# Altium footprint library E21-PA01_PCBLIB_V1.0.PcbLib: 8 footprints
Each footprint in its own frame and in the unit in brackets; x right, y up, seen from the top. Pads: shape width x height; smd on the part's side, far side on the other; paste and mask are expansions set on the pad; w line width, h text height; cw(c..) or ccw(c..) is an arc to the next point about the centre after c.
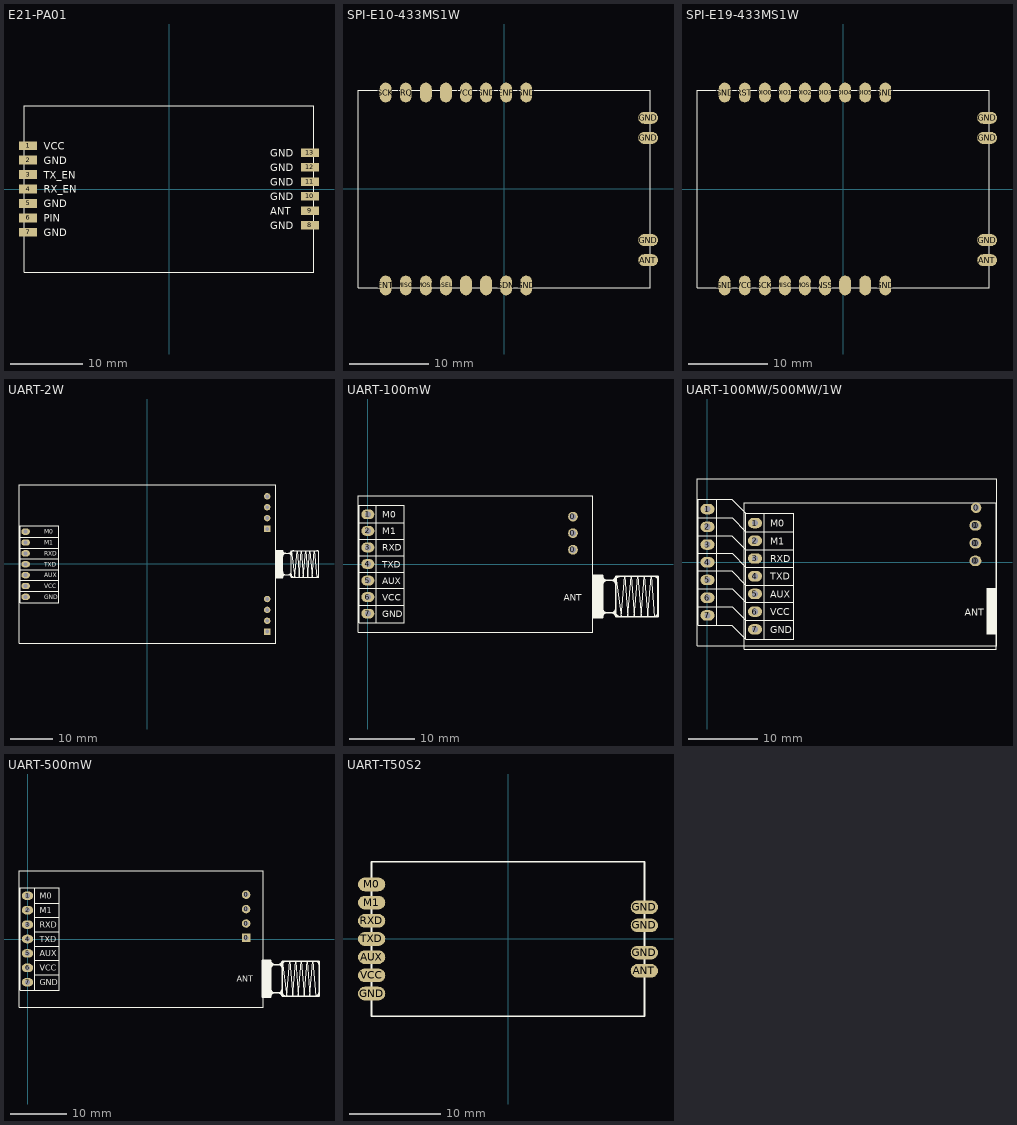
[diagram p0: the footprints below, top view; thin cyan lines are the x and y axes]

## E21-PA01 [mm]
pads (13):
  rect 2.5x1.2 smd: 1(-19.5,6) 2(-19.5,4) 3(-19.5,2) 4(-19.5,0) 5(-19.5,-2) 6(-19.5,-4) 7(-19.5,-6) 8(19.5,-5) 9(19.5,-3) 10(19.5,-1) 11(19.5,1) 12(19.5,3) 13(19.5,5)
TopOverlay:
  lines w0.1: -20,-11.5 20,-11.5 20,11.5 -20,11.5 -20,-11.5
  text "GND" at -17.35,3.45 h1
  text "TX_EN" at -17.35,1.45 h1
  text "PIN" at -17.35,-4.55 h1
  text "GND" at -17.35,-6.55 h1
  text "VCC" at -17.35,5.45 h1
  text "RX_EN" at -17.35,-0.55 h1
  text "GND" at -17.35,-2.55 h1
  text "GND" at 14,4.45 h1
  text "ANT" at 14,-3.55 h1
  text "GND" at 14,-1.55 h1
  text "GND" at 14,0.45 h1
  text "GND" at 14,2.45 h1
  text "GND" at 14,-5.55 h1

## SPI-E10-433MS1W [mm]
pads (20):
  oval 2.5x1.5 smd: ANT(18.2,-9) GND(18.2,-6.46) GND(18.2,6.46) GND(18.2,9)
  oval 1.5x2.5 smd: ENP(0.24,12.2) ENT(-15,-12.2) GND(-2.3,12.2) GND(2.78,-12.2) GND(2.78,12.2) GPIO0(-7.38,12.2) GPIO1(-9.92,12.2) GPIO2(-4.84,-12.2) GPIO3(-2.3,-12.2) IRQ(-12.46,12.2) MISO(-12.46,-12.2) MOSI(-9.92,-12.2) nSEL(-7.38,-12.2) SCK(-15,12.2) SDN(0.24,-12.2) VCC(-4.84,12.2)
TopOverlay:
  lines w0.1: -18.5,-12.5 18.5,-12.5 18.5,12.5 -18.5,12.5 -18.5,-12.5

## SPI-E19-433MS1W [mm]
pads (22):
  oval 2.5x1.5 smd: ANT(18.2,-9) GND(18.2,-6.46) GND(18.2,6.46) GND(18.2,9)
  oval 1.5x2.5 smd: CONT1(0.24,-12.2) CONT2(2.78,-12.2) DIO0(-9.92,12.2) DIO1(-7.38,12.2) DIO2(-4.84,12.2) DIO3(-2.3,12.2) DIO4(0.24,12.2) DIO5(2.78,12.2) GND(-15,-12.2) GND(-15,12.2) GND(5.32,-12.2) GND(5.32,12.2) MISO(-7.38,-12.2) MOSI(-4.84,-12.2) NSS(-2.3,-12.2) RST(-12.46,12.2) SCK(-9.92,-12.2) VCC(-12.46,-12.2)
TopOverlay:
  lines w0.1: -18.5,-12.5 -18.5,12.5 18.5,12.5 18.5,-12.5 -18.5,-12.5

## UART-2W [mm]
pads (18):
  oval 2x1.5 hole 0.9: 1(-28.46,7.56) 2(-28.46,5.02) 3(-28.46,2.48) 4(-28.46,-0.06) 5(-28.46,-2.6) 6(-28.46,-5.14) 7(-28.46,-7.68)
  rect 4.5x1.2 on Top Overlay: 1(27.41,0)
  rect 4.5x2 on Top Overlay: 2(27.41,-3.15) 2(27.41,3.15)
  rect 1.5x1.5 hole 0.9: 8(28,-15.81) 12(28,8.19)
  round 1.5 hole 0.9: 8(28,-13.27) 10(28,-10.73) 11(28,-8.19) 13(28,10.73) 14(28,13.27) 15(28,15.81)
TopOverlay:
  rectangle: 30.1,-3.25 31.6,3.25
  rectangle: 30.1,-3.245 31.6,3.255
  lines w0.1: -29.76,-6.4 -24.55,-6.4 ; -29.76,-3.82 -24.5,-3.82 ; -29.76,-1.32 -24.45,-1.32 ; -29.76,1.21 -24.4,1.21 ; -29.76,3.73 -24.5,3.73 ; -29.76,6.28 -24.75,6.28 ; -25,-6.4 -20.71,-6.4 ; -25,-3.82 -20.71,-3.82 ; -25,-1.32 -20.71,-1.32 ; -25,1.21 -20.71,1.21 ; -25,3.73 -20.71,3.73 ; -25,6.28 -20.71,6.28 ; 34.45,-3.1 34.97,3.1 ; 34.45,-3.1 33.6,3.1 34.45,-3.1 ; 34.45,-3.1 34.97,3.1 ; 34.97,3.1 35.48,-3.1 ; 34.97,3.1 35.48,-3.1 ; 35.48,-3.1 35.99,3.1 ; 35.48,-3.1 35.99,3.1 ; 35.99,3.1 36.47,-3.1 ; 35.99,3.1 36.47,-3.1 ; 36.47,-3.1 36.99,3.1 ; 36.47,-3.1 36.99,3.1 ; 36.99,3.1 37.5,-3.1 ; 36.99,3.1 37.5,-3.1 ; 37.5,-3.1 37.99,3.1 ; 37.5,-3.1 37.99,3.1 ; 37.99,3.1 38.51,-3.1 ; 37.99,3.1 38.51,-3.1 ; 38.51,-3.1 39.03,3.1 ; 38.51,-3.1 39.03,3.1 ; 39.03,3.1 39.54,-3.1 39.03,3.1 ; -30,-18.5 -30,18.5 30,18.5 30,-18.5 -30,-18.5 ; -29.76,-9.06 -29.76,8.94 -25,8.94 -20.71,8.94 -20.71,-9.06 -25,-9.06 -29.76,-9.06
  lines w0.254: 30.1,-3.25 31.6,-3.25 ; 30.1,-3.25 30.1,3.25 ; 30.1,-3.25 31.6,-3.25 ; 30.1,-3.25 30.1,3.25 ; 30.1,3.25 31.6,3.25 ; 30.1,3.25 31.6,3.25 ; 31.6,-3.25 31.6,3.25 ; 31.6,-3.25 31.6,3.25 ; 31.6,-1.85 ccw(c32.25,-1.85) 32.25,-2.5 ; 31.6,-1.85 ccw(c32.25,-1.85) 32.25,-2.5 ; 31.6,-1.85 31.6,-1.48 31.6,-1.85 ; 31.6,1.8 cw(c32.3,1.8) 32.3,2.5 ; 31.6,1.8 cw(c32.3,1.8) 32.3,2.5 ; 31.6,1.8 31.6,0.88 31.6,1.8 ; 31.6,3.13 ccw(c32.23,3.13) 32.23,2.5 ; 31.6,3.13 ccw(c32.23,3.13) 32.23,2.5 ; 31.6,3.13 31.6,3.25 ; 31.6,3.13 31.6,3.25 ; 32.15,-2.5 ccw(c32.15,-3.05) 31.6,-3.05 cw(c32.15,-3.05) 32.15,-2.5 ; 32.15,-2.5 33,-2.5 ; 32.15,-2.5 33,-2.5 ; 32.23,2.5 33,2.5 ; 32.23,2.5 33,2.5 ; 32.25,-2.5 32.97,-2.5 ; 32.25,-2.5 32.97,-2.5 ; 32.3,2.5 33,2.5 ; 32.3,2.5 33,2.5 ; 32.97,-2.5 ccw(c32.97,-1.87) 33.6,-1.87 cw(c32.97,-1.87) 32.97,-2.5 ; 33,-2.5 cw(c33,-3.1) 33.6,-3.1 ; 33,-2.5 cw(c33,-3.1) 33.6,-3.1 ; 33,2.5 cw(c33,1.9) 33.6,1.9 ccw(c33,1.9) 33,2.5 ; 33,2.5 ccw(c33,3.1) 33.6,3.1 ; 33,2.5 ccw(c33,3.1) 33.6,3.1 ; 33.6,-3.1 33.6,3.1 ; 33.6,-3.1 40.1,-3.1 ; 33.6,-3.1 33.6,3.1 ; 33.6,-3.1 40.1,-3.1 ; 33.6,3.1 40.1,3.1 ; 33.6,3.1 40.1,3.1 ; 34.28,-3.1 cw(c34.28,-2.42) 33.6,-2.42 ccw(c34.28,-2.42) 34.28,-3.1 ; 34.28,-3.1 34.43,-3.1 34.28,-3.1 ; 39.48,-3.1 ccw(c39.48,-2.48) 40.1,-2.48 cw(c39.48,-2.48) 39.48,-3.1 ; 39.48,-3.1 39.25,-3.1 39.48,-3.1 ; 39.56,3.1 cw(c39.56,2.56) 40.1,2.56 ccw(c39.56,2.56) 39.56,3.1 ; 39.56,3.1 39.16,3.1 39.56,3.1 ; 40.1,-3.1 40.1,3.1 ; 40.1,-3.1 40.1,3.1 ; 31.43,-2.5 33.6,-2.5 31.43,-2.5 ; 31.6,2.5 33.6,2.5 31.6,2.5 ; 33.6,2.49 cw(c34.21,2.49) 34.21,3.1 ccw(c34.21,2.49) 33.6,2.49
  text "M0" at -24.11,7.02 h1
  text "M1" at -24.11,4.48 h1
  text "RXD" at -24.11,1.94 h1
  text "TXD" at -24.11,-0.6 h1
  text "AUX" at -24.11,-3.14 h1
  text "VCC" at -24.11,-5.68 h1
  text "GND" at -24.11,-8.22 h1

## UART-100mW [mm]
pads (10):
  round 1.5 hole 1: 0(31.49,2.19) 0(31.49,4.73) 0(31.49,7.27)
  oval 2x1.5 hole 0.9: 1(0,7.62) 2(0,5.08) 3(0,2.54) 4(0,0) 5(0,-2.54) 6(0,-5.08) 7(0,-7.62)
TopOverlay:
  rectangle: 34.54,-8.25 36.04,-1.75
  rectangle: 34.54,-8.245 36.04,-1.745
  lines w0.1: 38.89,-8.1 39.41,-1.9 ; 38.89,-8.1 38.04,-1.9 38.89,-8.1 ; 38.89,-8.1 39.41,-1.9 ; 39.41,-1.9 39.92,-8.1 ; 39.41,-1.9 39.92,-8.1 ; 39.92,-8.1 40.43,-1.9 ; 39.92,-8.1 40.43,-1.9 ; 40.43,-1.9 40.91,-8.1 ; 40.43,-1.9 40.91,-8.1 ; 40.91,-8.1 41.43,-1.9 ; 40.91,-8.1 41.43,-1.9 ; 41.43,-1.9 41.94,-8.1 ; 41.43,-1.9 41.94,-8.1 ; 41.94,-8.1 42.43,-1.9 ; 41.94,-8.1 42.43,-1.9 ; 42.43,-1.9 42.95,-8.1 ; 42.43,-1.9 42.95,-8.1 ; 42.95,-8.1 43.47,-1.9 ; 42.95,-8.1 43.47,-1.9 ; 43.47,-1.9 43.98,-8.1 43.47,-1.9 ; -1.51,-10.5 34.558,-10.5 34.558,10.5 -1.51,10.5 -1.51,-10.5
  lines w0.127: -1.3,-9 1.3,-9 1.3,9 -1.3,9 -1.3,-9
  lines w0.152: -1.31,3.8 1.3,3.8 ; -1.3,-3.76 1.3,-3.76 5.59,-3.76 ; -1.29,-6.34 1.3,-6.34 5.59,-6.34 ; -1.29,-1.26 1.3,-1.26 5.59,-1.26 ; -1.29,1.27 1.3,1.27 5.59,1.27 ; -1.29,6.36 1.3,6.36 ; 1.3,-9 5.59,-9 5.59,9 1.3,9 ; 1.3,3.79 5.59,3.79 ; 1.3,6.34 5.59,6.34
  lines w0.254: 34.54,-8.25 36.04,-8.25 ; 34.54,-8.25 34.54,-1.75 ; 34.54,-8.25 36.04,-8.25 ; 34.54,-8.25 34.54,-1.75 ; 34.54,-1.75 36.04,-1.75 ; 34.54,-1.75 36.04,-1.75 ; 36.04,-8.25 36.04,-1.75 ; 36.04,-8.25 36.04,-1.75 ; 36.04,-6.85 ccw(c36.69,-6.85) 36.69,-7.5 ; 36.04,-6.85 ccw(c36.69,-6.85) 36.69,-7.5 ; 36.04,-6.85 36.04,-6.48 36.04,-6.85 ; 36.04,-3.2 cw(c36.74,-3.2) 36.74,-2.5 ; 36.04,-3.2 cw(c36.74,-3.2) 36.74,-2.5 ; 36.04,-3.2 36.04,-4.12 36.04,-3.2 ; 36.04,-1.87 ccw(c36.67,-1.87) 36.67,-2.5 ; 36.04,-1.87 ccw(c36.67,-1.87) 36.67,-2.5 ; 36.04,-1.87 36.04,-1.75 ; 36.04,-1.87 36.04,-1.75 ; 36.59,-7.5 ccw(c36.59,-8.05) 36.04,-8.05 cw(c36.59,-8.05) 36.59,-7.5 ; 36.59,-7.5 37.44,-7.5 ; 36.59,-7.5 37.44,-7.5 ; 36.67,-2.5 37.44,-2.5 ; 36.67,-2.5 37.44,-2.5 ; 36.69,-7.5 37.41,-7.5 ; 36.69,-7.5 37.41,-7.5 ; 36.74,-2.5 37.44,-2.5 ; 36.74,-2.5 37.44,-2.5 ; 37.41,-7.5 ccw(c37.41,-6.87) 38.04,-6.87 cw(c37.41,-6.87) 37.41,-7.5 ; 37.44,-7.5 cw(c37.44,-8.1) 38.04,-8.1 ; 37.44,-7.5 cw(c37.44,-8.1) 38.04,-8.1 ; 37.44,-2.5 cw(c37.44,-3.1) 38.04,-3.1 ccw(c37.44,-3.1) 37.44,-2.5 ; 37.44,-2.5 ccw(c37.44,-1.9) 38.04,-1.9 ; 37.44,-2.5 ccw(c37.44,-1.9) 38.04,-1.9 ; 38.04,-8.1 38.04,-1.9 ; 38.04,-8.1 44.54,-8.1 ; 38.04,-8.1 38.04,-1.9 ; 38.04,-8.1 44.54,-8.1 ; 38.04,-1.9 44.54,-1.9 ; 38.04,-1.9 44.54,-1.9 ; 38.72,-8.1 cw(c38.72,-7.42) 38.04,-7.42 ccw(c38.72,-7.42) 38.72,-8.1 ; 38.72,-8.1 38.87,-8.1 38.72,-8.1 ; 43.92,-8.1 ccw(c43.92,-7.48) 44.54,-7.48 cw(c43.92,-7.48) 43.92,-8.1 ; 43.92,-8.1 43.69,-8.1 43.92,-8.1 ; 44,-1.9 cw(c44,-2.44) 44.54,-2.44 ccw(c44,-2.44) 44,-1.9 ; 44,-1.9 43.6,-1.9 44,-1.9 ; 44.54,-8.1 44.54,-1.9 ; 44.54,-8.1 44.54,-1.9 ; 35.87,-7.5 38.04,-7.5 35.87,-7.5 ; 36.04,-2.5 38.04,-2.5 36.04,-2.5 ; 38.04,-2.51 cw(c38.65,-2.51) 38.65,-1.9 ccw(c38.65,-2.51) 38.04,-2.51
  text "GND" at 2.19,-8.16 h1
  text "VCC" at 2.19,-5.62 h1
  text "AUX" at 2.19,-3.08 h1
  text "TXD" at 2.19,-0.54 h1
  text "RXD" at 2.19,2 h1
  text "M1" at 2.19,4.54 h1
  text "M0" at 2.19,7.08 h1
  text "ANT" at 30.05,-5.64 h1

## UART-100MW/500MW/1W [mm]
pads (21):
  round 1.5 hole 1: 0(38.3,0.19) 0(38.3,2.73) 0(38.3,5.27)
  round 1.5 hole 0.9: 0(38.5,0.19) 0(38.5,2.73) 0(38.5,5.27) 0(38.5,7.81)
  oval 2x1.5 hole 0.9: 1(0,7.62) 1(6.81,5.62) 2(0,5.08) 2(6.81,3.08) 3(0,2.54) 3(6.81,0.54) 4(0,0) 4(6.81,-2) 5(0,-2.54) 5(6.81,-4.54) 6(0,-5.08) 6(6.81,-7.08) 7(0,-7.62) 7(6.81,-9.62)
TopOverlay:
  region: 41.368,-3.683 40.005,-3.683 40.005,-10.35 41.368,-10.35
  lines w0.1: -1.5,-12 -1.5,12 41.5,12 41.5,-12 -1.5,-12 ; 5.3,-12.5 5.3,8.5 41.368,8.5 41.368,-12.5 5.3,-12.5
  lines w0.127: -1.3,-9 -1.3,9 1.3,9 1.3,-9 -1.3,-9 ; 5.51,-11 5.51,7 8.11,7 8.11,-11 5.51,-11
  lines w0.152: -1.3,-6.35 3.53,-6.35 5.52,-8.34 8.11,-8.34 12.4,-8.34 ; -1.3,-3.78 3.53,-3.78 5.51,-5.76 8.11,-5.76 12.4,-5.76 ; -1.3,-1.25 3.51,-1.25 5.52,-3.26 8.11,-3.26 12.4,-3.26 ; -1.3,1.27 3.52,1.27 5.52,-0.73 8.11,-0.73 12.4,-0.73 ; -1.3,3.8 3.5,3.8 5.5,1.8 8.11,1.8 ; -1.28,6.36 3.52,6.36 5.52,4.36 8.11,4.36 ; 1.3,-9 3.51,-9 5.51,-11 ; 1.3,9 3.51,9 5.51,7 ; 8.11,-11 12.4,-11 12.4,7 8.11,7 ; 8.11,1.79 12.4,1.79 ; 8.11,4.34 12.4,4.34
  text "ANT" at 36.86,-7.64 h1
  text "M0" at 9,5.08 h1
  text "M1" at 9,2.54 h1
  text "RXD" at 9,0 h1
  text "TXD" at 9,-2.54 h1
  text "AUX" at 9,-5.08 h1
  text "VCC" at 9,-7.62 h1
  text "GND" at 9,-10.16 h1
3D body: height 7.74, standoff 1.34, extent 37.7,-10.25 56,-3.85
3D body: height 5.54, standoff -5.66, extent -1.209,-8.83 1.289,8.95
3D body: height 3.54, standoff 2.54, extent -1.5,-12 41.5,12
3D body: height 6.54, standoff 3.54, extent 1.55,-10.65 35.65,10.5

## UART-500mW [mm]
pads (11):
  rect 1.5x1.5 hole 0.9: 0(38.5,0.19)
  round 1.5 hole 0.9: 0(38.5,2.73) 0(38.5,5.27) 0(38.5,7.81)
  oval 2x1.5 hole 0.9: 1(0,7.62) 2(0,5.08) 3(0,2.54) 4(0,0) 5(0,-2.54) 6(0,-5.08) 7(0,-7.62)
TopOverlay:
  rectangle: 41.35,-10.245 42.85,-3.745
  rectangle: 41.35,-10.25 42.85,-3.75
  lines w0.1: 45.7,-10.1 44.85,-3.9 45.7,-10.1 ; 45.7,-10.1 46.22,-3.9 ; 45.7,-10.1 46.22,-3.9 ; 46.22,-3.9 46.73,-10.1 ; 46.22,-3.9 46.73,-10.1 ; 46.73,-10.1 47.24,-3.9 ; 46.73,-10.1 47.24,-3.9 ; 47.24,-3.9 47.72,-10.1 ; 47.24,-3.9 47.72,-10.1 ; 47.72,-10.1 48.24,-3.9 ; 47.72,-10.1 48.24,-3.9 ; 48.24,-3.9 48.75,-10.1 ; 48.24,-3.9 48.75,-10.1 ; 48.75,-10.1 49.24,-3.9 ; 48.75,-10.1 49.24,-3.9 ; 49.24,-3.9 49.76,-10.1 ; 49.24,-3.9 49.76,-10.1 ; 49.76,-10.1 50.28,-3.9 ; 49.76,-10.1 50.28,-3.9 ; 50.28,-3.9 50.79,-10.1 50.28,-3.9 ; -1.5,-12 -1.5,12 41.5,12 41.5,-12 -1.5,-12
  lines w0.127: 1.3,-9 1.3,9 ; 1.3,-9 -1.3,-9 -1.3,9 1.3,9 ; 1.3,-9 1.3,9
  lines w0.152: 1.3,-9 5.59,-9 5.59,9 1.3,9 ; 1.3,-6.34 5.59,-6.34 ; 1.3,-3.76 5.59,-3.76 ; 1.3,-1.26 5.59,-1.26 ; 1.3,1.27 5.59,1.27 ; 1.3,3.79 5.59,3.79 ; 1.3,6.34 5.59,6.34
  lines w0.254: 41.35,-10.25 41.35,-3.75 ; 41.35,-10.25 42.85,-10.25 ; 41.35,-10.25 41.35,-3.75 ; 41.35,-10.25 42.85,-10.25 ; 41.35,-3.75 42.85,-3.75 ; 41.35,-3.75 42.85,-3.75 ; 42.85,-10.25 42.85,-3.75 ; 42.85,-10.25 42.85,-3.75 ; 42.85,-8.85 ccw(c43.5,-8.85) 43.5,-9.5 ; 42.85,-8.85 ccw(c43.5,-8.85) 43.5,-9.5 ; 42.85,-8.85 42.85,-8.48 42.85,-8.85 ; 42.85,-5.2 cw(c43.55,-5.2) 43.55,-4.5 ; 42.85,-5.2 cw(c43.55,-5.2) 43.55,-4.5 ; 42.85,-5.2 42.85,-6.12 42.85,-5.2 ; 42.85,-3.87 ccw(c43.48,-3.87) 43.48,-4.5 ; 42.85,-3.87 ccw(c43.48,-3.87) 43.48,-4.5 ; 42.85,-3.87 42.85,-3.75 ; 42.85,-3.87 42.85,-3.75 ; 43.4,-9.5 ccw(c43.4,-10.05) 42.85,-10.05 cw(c43.4,-10.05) 43.4,-9.5 ; 43.4,-9.5 44.25,-9.5 ; 43.4,-9.5 44.25,-9.5 ; 43.48,-4.5 44.25,-4.5 ; 43.48,-4.5 44.25,-4.5 ; 43.5,-9.5 44.22,-9.5 ; 43.5,-9.5 44.22,-9.5 ; 43.55,-4.5 44.25,-4.5 ; 43.55,-4.5 44.25,-4.5 ; 44.22,-9.5 ccw(c44.22,-8.87) 44.85,-8.87 cw(c44.22,-8.87) 44.22,-9.5 ; 44.25,-9.5 cw(c44.25,-10.1) 44.85,-10.1 ; 44.25,-9.5 cw(c44.25,-10.1) 44.85,-10.1 ; 44.25,-4.5 ccw(c44.25,-3.9) 44.85,-3.9 ; 44.25,-4.5 cw(c44.25,-5.1) 44.85,-5.1 ccw(c44.25,-5.1) 44.25,-4.5 ; 44.25,-4.5 ccw(c44.25,-3.9) 44.85,-3.9 ; 44.85,-10.1 51.35,-10.1 ; 44.85,-10.1 44.85,-3.9 ; 44.85,-10.1 51.35,-10.1 ; 44.85,-10.1 44.85,-3.9 ; 44.85,-3.9 51.35,-3.9 ; 44.85,-3.9 51.35,-3.9 ; 45.53,-10.1 cw(c45.53,-9.42) 44.85,-9.42 ccw(c45.53,-9.42) 45.53,-10.1 ; 45.53,-10.1 45.68,-10.1 45.53,-10.1 ; 50.73,-10.1 ccw(c50.73,-9.48) 51.35,-9.48 cw(c50.73,-9.48) 50.73,-10.1 ; 50.73,-10.1 50.5,-10.1 50.73,-10.1 ; 50.81,-3.9 cw(c50.81,-4.44) 51.35,-4.44 ccw(c50.81,-4.44) 50.81,-3.9 ; 50.81,-3.9 50.41,-3.9 50.81,-3.9 ; 51.35,-10.1 51.35,-3.9 ; 51.35,-10.1 51.35,-3.9 ; 42.68,-9.5 44.85,-9.5 42.68,-9.5 ; 42.85,-4.5 44.85,-4.5 42.85,-4.5 ; 44.85,-4.51 cw(c45.46,-4.51) 45.46,-3.9 ccw(c45.46,-4.51) 44.85,-4.51
  text "ANT" at 36.83,-7.57 h1
  text "GND" at 2.19,-8.16 h1
  text "VCC" at 2.19,-5.62 h1
  text "AUX" at 2.19,-3.08 h1
  text "TXD" at 2.19,-0.54 h1
  text "RXD" at 2.19,2 h1
  text "M1" at 2.19,4.54 h1
  text "M0" at 2.19,7.08 h1

## UART-T50S2 [mm]
pads (11):
  oval 3x1.5 smd: ANT(15,-3.5) AUX(-15,-2) GND(-15,-6) GND(15,-1.5) GND(15,1.5) GND(15,3.5) M0(-15,6) M1(-15,4) RXD(-15,2) TXD(-15,0) VCC(-15,-4)
TopOverlay:
  lines w0.2: -15,-8.5 15,-8.5 15,8.5 -15,8.5 -15,-8.5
